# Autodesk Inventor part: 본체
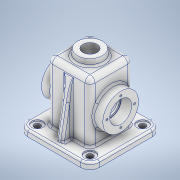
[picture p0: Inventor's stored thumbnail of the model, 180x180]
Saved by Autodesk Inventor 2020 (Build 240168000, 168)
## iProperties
Created: 2021-07
Part Number: 본체
Material: 알루미늄 6061
Document SubType Name: Modeling
Designer: Owner
Density: 2.7 g/cm^3
Appearance: 알루미늄 - 평지
Author: Owner
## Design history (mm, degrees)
sketch "스케치1"
  geometry: L1 (-34, 34)-(34, 34); L2 (34, 34)-(34, -34); L3 (34, -34)-(-34, -34); L4 (-34, -34)-(-34, 34); L5 (-34, 34)-(34, -34); L6 (34, 34)-(-34, -34); 1 further point
  constraints: 12 end point, 2 midpoint, 2 parallel, 1 horizontal, 1 perpendicular
  dimensions: "d0" = 68 distance of L2.end L3.end; "d1" = 68 distance of L1.end L2.end
extrude "돌출1" new body sketch "스케치1" distance "d2" = 105; taper "d3" = 0 deg
sketch "스케치2"
  geometry: L1 (-29, 29)-(29, 29); L2 (29, 29)-(29, -29); L3 (29, -29)-(-29, -29); L4 (-29, -29)-(-29, 29); L5 (-29, 29)-(29, -29); L6 (29, 29)-(-29, -29); 1 further point
  constraints: 12 end point, 2 midpoint, 2 parallel, 1 horizontal, 1 perpendicular
  dimensions: "d4" = 58 distance of L2.end L3.end; "d5" = 58 distance of L1.end L2.end
extrude "돌출2" cut sketch "스케치2" distance "d6" = 100; taper "d7" = 0 deg
fillet "모깎기1" dims "d8" = 8
sketch "스케치3"
  geometry: L1 (-57, 57)-(57, 57); L2 (57, 57)-(57, -57); L3 (57, -57)-(-57, -57); L4 (-57, -57)-(-57, 57); L5 (-57, 57)-(57, -57); L6 (57, 57)-(-57, -57); L7 (34, 26)-(34, -26) reference; L8 (-26, 34)-(26, 34) reference; L9 (-34, -26)-(-34, 26) reference; L10 (26, -34)-(-26, -34) reference; L11 (21, -29)-(-21, -29) reference; L12 (-29, -21)-(-29, 21) reference; L13 (-21, 29)-(21, 29) reference; L14 (29, 21)-(29, -21) reference; A1 r 8 centre (26, -26) between (26, -34) and (34, -26) reference; A2 r 8 centre (26, 26) between (34, 26) and (26, 34) reference; A3 r 8 centre (-26, 26) between (-26, 34) and (-34, 26) reference; A4 r 8 centre (-26, -26) between (-34, -26) and (-26, -34) reference; A5 r 8 centre (-21, -21) between (-29, -21) and (-21, -29) reference; A6 r 8 centre (-21, 21) between (-21, 29) and (-29, 21) reference; A7 r 8 centre (21, 21) between (29, 21) and (21, 29) reference; A8 r 8 centre (21, -21) between (21, -29) and (29, -21) reference; 1 further point
  constraints: 12 end point, 2 midpoint, 2 parallel, 1 horizontal, 1 perpendicular
  dimensions: "d9" = 114 distance of L2.end L3.end; "d10" = 114 distance of L1.end L2.end
extrude "돌출3" join sketch "스케치3" distance "d11" = 10; taper "d12" = 0 deg
fillet "모깎기2" dims "d13" = 15
node "작업 평면1"
sketch "스케치4"
  geometry: C1 r 20 at (0, 0); 1 further point
  constraints: 1 centre point, 1 coincident
  dimensions: "d16" = 40 diameter of C1
extrude "돌출4" join sketch "스케치4" stored distance "d17" = 10; taper "d18" = 8 deg
node "작업 평면2"
sketch "스케치5"
  geometry: L1 (26, -97)-(26, -45); C1 r 28.5 at (26, -45)
  constraints: 2 end point, 1 centre point, 1 coincident, 1 vertical
  dimensions: "d20" = 52 distance of L1.start L1.end; "d21" = 57 diameter of C1
extrude "돌출5" join sketch "스케치5" distance "d22" = 17.25; taper "d23" = 0 deg
node "작업 평면3"
sketch "스케치6"
  geometry: L1 (26, -97)-(26, -45); C1 r 28.5 at (26, -45)
  constraints: 2 end point, 1 centre point, 1 coincident, 1 vertical
  dimensions: "d25" = 52 distance of L1.start L1.end; "d26" = 57 diameter of C1
extrude "돌출6" join sketch "스케치6" distance "d27" = 19.25; taper "d28" = 0 deg
sketch "스케치7" dims "d29" = 44
  geometry: C1 r 2.371 at (0, 22); C2 r 2.371 at (-22, 0); C3 r 2.371 at (0, -22); C4 r 2.371 at (22, 0); 2 further points
  constraints: 4 centre point, 1 vertical alignment, 11 other
  dimensions: "d32" = 360 deg dimension on point (0, 0) C1.centre (derived)
hole "구멍1" sketch "스케치7" at (-22, 0), (0, -22), (22, 0), (0, 22) diameter "d34" = 3.242; stored, may be unused: countersink angle "d38" = 90 deg, drill point angle "d40" = 118 deg; dims "d35" = 8, "d36" = 4, "d37" = 2, "d39" = 10
sketch "스케치8"
  geometry: C1 r 1.621 at (0, -22) reference; C2 r 1.621 at (0, -22); C3 r 1.621 at (22, 0) reference; C4 r 1.621 at (22, 0); C5 r 1.622 at (0, 22); C6 r 1.779 at (-22, 0); A1 r 22 centre (0, 0) between (0, 22) and (-22, 0); 1 further point
  constraints: 5 centre point, 2 coincident, 2 point on circle
  dimensions: "d41" = 44 diameter of A1
hole "구멍2" sketch "스케치8" at (0, 22), (22, 0), (0, -22), (-22, 0) diameter "d42" = 3.242; stored, may be unused: countersink angle "d46" = 90 deg, drill point angle "d48" = 118 deg; dims "d43" = 8, "d44" = 4, "d45" = 2, "d47" = 10
sketch "스케치9"
  geometry: C1 r 17.5 at (0, 0); 1 further point
  constraints: 1 centre point
  dimensions: "d49" = 35 diameter of C1
extrude "돌출7" cut sketch "스케치9" distance "d50" = 17; taper "d51" = 0 deg
sketch "스케치10"
  geometry: C1 r 17.5 at (0, 0); 1 further point
  constraints: 1 centre point
extrude "돌출8" cut sketch "스케치10" distance "d52" = 17; taper "d53" = 0 deg
sketch "스케치11"
  geometry: C1 r 15 at (0, 0); 1 further point
  constraints: 1 centre point
  dimensions: "d54" = 30 diameter of C1
extrude "돌출9" cut sketch "스케치11" distance "d55" = 3; taper "d56" = 0 deg
sketch "스케치12"
  geometry: C1 r 15 at (0, 0); 1 further point
  constraints: 1 centre point
  dimensions: "d57" = 30 diameter of C1
extrude "돌출10" cut sketch "스케치12" distance "d58" = 3; taper "d59" = 0 deg
fillet "모깎기4" dims "d60" = 0.3
sketch "스케치13"
  geometry: C1 r 12.5 at (0, 0); 1 further point
  constraints: 1 centre point, 1 coincident
  dimensions: "d61" = 25 diameter of C1
hole "구멍3" sketch "스케치13" at (0, 0) diameter "d62" = 22.83494; stored, may be unused: countersink angle "d66" = 90 deg, drill point angle "d68" = 0 deg; dims "d63" = 50, "d64" = 4, "d65" = 2, "d67" = 59.3
node "작업 평면4"
fillet "모깎기5" dims "d75" = 3
sketch "스케치15"
  geometry: L1 (-36, 0)-(-36, 7) reference; L2 (-33, 10)-(-21, 10) reference; L3 (-28, 10)-(-18.531, 63.701); 1 further point
  constraints: 2 end point, 1 point on line
  dimensions: "d77" = 10 deg angle of L1 L3; "d78" = 8 distance from line of L1 L3.start
feature "리브1" sketch "스케치15" dims "d79" = 1, "d80" = 10, "d81" = 0, "d82" = 0, "d83" = 1, "d84" = 1
node "작업 평면5"
fillet "모깎기6" dims "d85" = 3
fillet "모깎기7" dims "d86" = 3
sketch "스케치16"
  geometry: C1 r 9 at (42, -42); C2 r 9 at (42, 42); C3 r 9 at (-42, 42); C4 r 9 at (-42, -42); A1 r 12 centre (42, -42) between (42, -54) and (54, -42) reference; A2 r 12 centre (42, 42) between (54, 42) and (42, 54) reference; A3 r 12 centre (-42, 42) between (-42, 54) and (-54, 42) reference; A4 r 12 centre (-42, -42) between (-54, -42) and (-42, -54) reference; 1 further point
  constraints: 4 centre point, 4 coincident
  dimensions: "d87" = 18 diameter of C1; "d88" = 18 diameter of C2; "d89" = 18 diameter of C3; "d90" = 18 diameter of C4
extrude "돌출11" cut sketch "스케치16" distance "d91" = 2; taper "d92" = 0 deg
sketch "스케치17"
  geometry: C1 r 9 at (0, 0) reference; C2 r 5 at (0, 0); C3 r 9 at (-84, 0) reference; C4 r 5 at (-84, 0); C5 r 9 at (-84, -84) reference; C6 r 5 at (-84, -84); C7 r 9 at (0, -84) reference; C8 r 5 at (0, -84); 1 further point
  constraints: 4 centre point, 4 coincident
  dimensions: "d93" = 10 diameter of C2; "d94" = 10 diameter of C4; "d95" = 10 diameter of C6; "d96" = 10 diameter of C8
extrude "돌출12" cut sketch "스케치17" stored distance "d97" = 2; taper "d98" = 0 deg
fillet "모깎기8" dims "d99" = 3
sketch "스케치18"
  geometry: L1 (46, 18)-(6, 18) reference; L2 (37.417, 3)-(14.583, 3) reference; 3 further points
  constraints: 1 midpoint, 1 vertical alignment, 1 other
  dimensions: "d102" = 25 distance from line of point (26, -7) L1
extrude "돌출13" join sketch "스케치18" distance "d103" = 0.5; taper "d104" = 0 deg
node "솔리드1"
mirror "미러1"
node "투영된 루프1"
feature "A9D066F2-1C7D-4E18-AEED-F7BC21143FA4" dims "d34" = 3.242, "d35" = 8, "d36" = 4, "d37" = 2, "d38" = 90 deg, "d39" = 10, "d40" = 118 deg
other parameters: "d15" = 105, "d19" = 15, "d24" = 15
